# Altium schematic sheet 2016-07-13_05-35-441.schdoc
size 220 x 124 mm; SheetNumber: 1; SheetTotal: 1
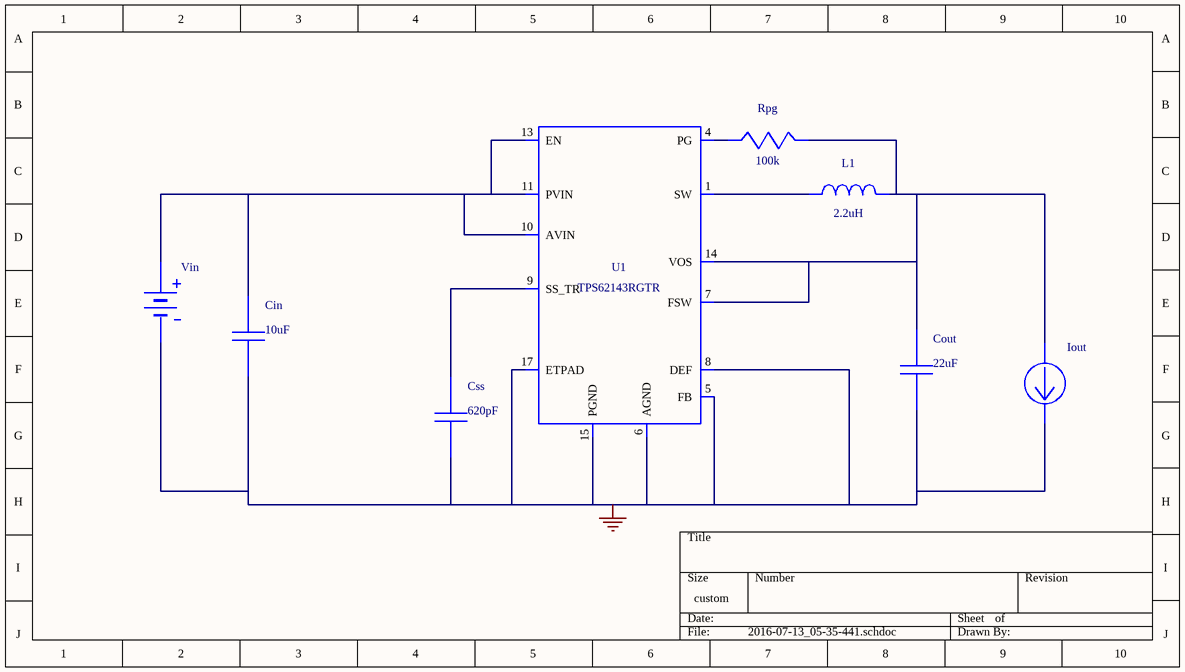
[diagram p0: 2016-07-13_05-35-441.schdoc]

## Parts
Cin  value 10uF  (hidden comment: TMK316BJ106KL-T)
Cout  value 22uF  (hidden comment: GRM31CR61A226KE19L)
Css  value 620pF  (hidden comment: CL21C621JBCNNNC)
Iout  WB_CURRENT_LOAD  (value not drawn)
L1  value 2.2uH  (hidden comment: XAL4020-222MEB)
Rpg  value 100k  (hidden comment: CRCW0402100KFKED)
U1  TPS62131RGTR  (value not drawn)
Vin  WB_BATTERY  (value not drawn)

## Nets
0: Cin.2 Cout.2 Css.2 Iout.2(-) U1.5(FB) U1.6(AGND) U1.8(DEF) U1.15(PGND) U1.16(PGND) U1.17(ETPAD) Vin.2(-)
NetCin_1: Cin.1 U1.10(AVIN) U1.11(PVIN) U1.12(PVIN) U1.13(EN) Vin.1(+)
NetCout_1: Cout.1 Iout.1(+) L1.2 Rpg.1 U1.7(FSW) U1.14(VOS)
NetCss_1: Css.1 U1.9(SS_TR)
NetL1_1: L1.1 U1.1(SW) U1.2(SW) U1.3(SW)
NetRpg_2: Rpg.2 U1.4(PG)

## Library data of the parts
Cin = TMK316BJ106KL-T: Manufacturer Name: Taiyo Yuden
Cout = GRM31CR61A226KE19L: GRM31CR61A226KE1; Manufacturer Name: MuRata
Css = CL21C621JBCNNNC: Manufacturer Name: Samsung Electro-Mechanics
L1 = XAL4020-222MEB: Manufacturer Name: Coilcraft
Rpg = CRCW0402100KFKED: Manufacturer Name: Vishay-Dale
U1 = TPS62131RGTR: TPS62143RGTR; Manufacturer Name: Texas Instruments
